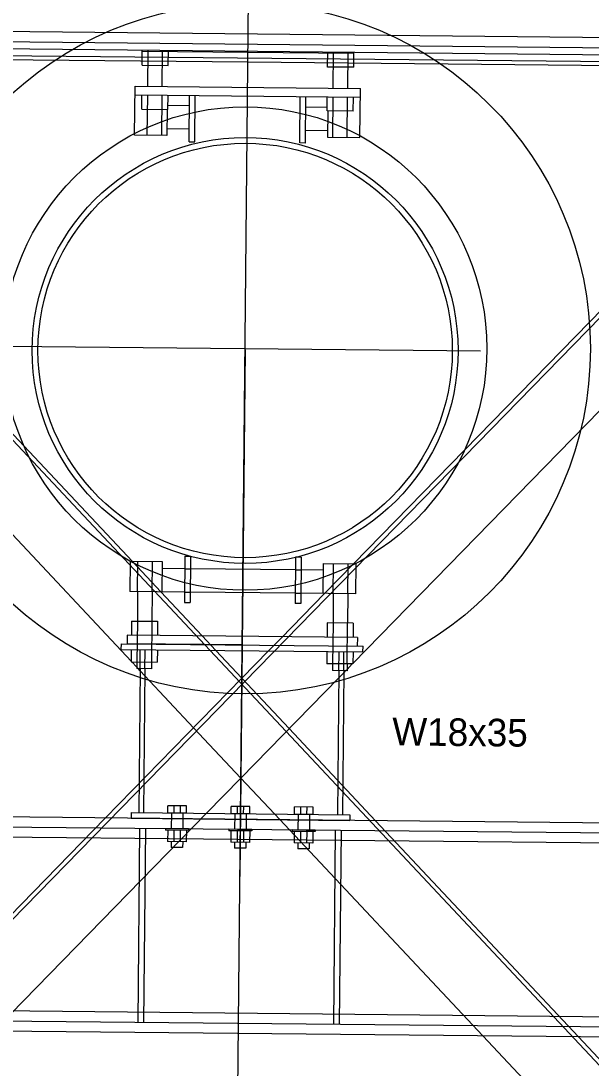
# Model space of a CAD drawing. Extents: x 632312 to 632885, y 378199 to 378534.
# Drawn here: x 632368.08 to 632372.21, y 378385.31 to 378392.89 of the extents above; entities that cross this region are included whole.
import ezdxf

# ---------------------------------------------------------------- set-up
doc = ezdxf.new("R2010")
doc.units = 0
for name, color, linetype in [('B_Boring', 7, 'Continuous'), ('R_Border', 7, 'Continuous'), ('R_Proposed Const Limits Cut', 7, 'Continuous'), ('R_Road Edge of Shoulder', 7, 'Continuous'), ('SHT_Dimensions', 7, 'Continuous')]:
    doc.layers.add(name, color=color, linetype=linetype)

msp = doc.modelspace()

# ---------------------------------------------------------------- linework, layer by layer
at = {"layer": 'B_Boring'}
for p, q in [((632375.2263, 378392.6104), (632364.2269, 378392.7198)), ((632375.2268, 378392.6608), (632364.2274, 378392.7702)), ((632368.9597, 378392.5654), (632368.9607, 378392.6727)), ((632370.4924, 378392.6503), (632368.9607, 378392.6655)), ((632369.0003, 378392.4123), (632369.0029, 378392.6723)), ((632369.1051, 378392.4113), (632369.1077, 378392.6713)), ((632369.1488, 378392.5635), (632369.1499, 378392.6708)), ((632370.3023, 378392.552), (632370.3033, 378392.6594)), ((632370.3429, 378392.399), (632370.3455, 378392.659)), ((632370.4477, 378392.3979), (632370.4503, 378392.6579)), ((632370.4914, 378392.5502), (632370.4925, 378392.6575)), ((632365.1844, 378392.6342), (632369.7259, 378392.5891)), ((632368.9597, 378392.5654), (632369.1488, 378392.5635)), ((632369.7259, 378392.5891), (632374.2673, 378392.5439)), ((632370.4914, 378392.5502), (632370.3023, 378392.552)), ((632368.9043, 378392.0583), (632368.9078, 378392.4132)), ((632368.9078, 378392.4132), (632370.5403, 378392.397)), ((632368.9072, 378392.35), (632370.5396, 378392.3338)), ((632368.9565, 378392.2474), (632368.9575, 378392.3495)), ((632368.9968, 378392.0574), (632368.9997, 378392.3491)), ((632369.1016, 378392.0564), (632369.1045, 378392.3481)), ((632369.1457, 378392.2455), (632369.1467, 378392.3477)), ((632369.2988, 378392.0103), (632369.3021, 378392.3461)), ((632369.3398, 378392.0099), (632369.3432, 378392.3457)), ((632370.1003, 378392.0023), (632370.1036, 378392.3381)), ((632370.1414, 378392.0019), (632370.1447, 378392.3377)), ((632370.2991, 378392.2341), (632370.3001, 378392.3362)), ((632370.3394, 378392.044), (632370.3423, 378392.3358)), ((632370.4442, 378392.043), (632370.4471, 378392.3347)), ((632370.4883, 378392.2322), (632370.4893, 378392.3343)), ((632370.5367, 378392.0421), (632370.5403, 378392.397)), ((632369.3013, 378392.2712), (632369.1459, 378392.2727)), ((632370.144, 378392.2628), (632370.2994, 378392.2613)), ((632368.9565, 378392.2474), (632369.1457, 378392.2455)), ((632369.1403, 378392.2456), (632369.1384, 378392.056)), ((632370.4883, 378392.2322), (632370.2991, 378392.2341)), ((632370.3045, 378392.234), (632370.3026, 378392.0444)), ((632369.1384, 378392.056), (632368.9043, 378392.0583)), ((632369.2997, 378392.1032), (632369.1389, 378392.1048)), ((632370.1423, 378392.0948), (632370.3031, 378392.0932)), ((632370.3026, 378392.0444), (632370.5367, 378392.0421)), ((632369.2988, 378392.0103), (632369.3398, 378392.0099)), ((632370.1414, 378392.0019), (632370.1003, 378392.0023)), ((632369.2689, 378389.0123), (632369.2656, 378388.6765)), ((632369.2689, 378389.0123), (632369.31, 378389.0119)), ((632369.31, 378389.0119), (632369.3067, 378388.6761)), ((632370.0705, 378389.0044), (632370.0672, 378388.6686)), ((632370.1116, 378389.004), (632370.0705, 378389.0044)), ((632370.1116, 378389.004), (632370.1082, 378388.6682)), ((632368.8736, 378388.9722), (632368.8714, 378388.7554)), ((632369.1077, 378388.9698), (632368.8736, 378388.9722)), ((632369.1056, 378388.7531), (632369.1077, 378388.9698)), ((632370.2698, 378388.7415), (632370.2719, 378388.9583)), ((632370.2719, 378388.9583), (632370.506, 378388.9559)), ((632370.506, 378388.9559), (632370.5039, 378388.7392)), ((632369.268, 378388.9195), (632369.1072, 378388.9211)), ((632370.0696, 378388.9115), (632369.3091, 378388.919)), ((632370.2714, 378388.9095), (632370.1106, 378388.9111)), ((632369.2663, 378388.7515), (632368.8714, 378388.7554)), ((632368.927, 378388.7548), (632368.9248, 378388.5413)), ((632369.0318, 378388.7538), (632369.0296, 378388.5403)), ((632370.0679, 378388.7435), (632369.3074, 378388.7511)), ((632370.5039, 378388.7392), (632370.109, 378388.7431)), ((632370.3436, 378388.7408), (632370.3414, 378388.5273)), ((632370.4484, 378388.7397), (632370.4462, 378388.5262)), ((632369.2656, 378388.6765), (632369.3067, 378388.6761)), ((632370.1082, 378388.6682), (632370.0672, 378388.6686)), ((632368.8827, 378388.5418), (632368.8816, 378388.4396)), ((632368.8827, 378388.5418), (632369.0718, 378388.5399)), ((632369.0718, 378388.5399), (632369.0708, 378388.4377)), ((632370.2993, 378388.5277), (632370.2982, 378388.4255)), ((632370.4884, 378388.5258), (632370.2993, 378388.5277)), ((632370.4884, 378388.5258), (632370.4874, 378388.4237)), ((632368.8512, 378388.4399), (632368.8506, 378388.3767)), ((632370.5178, 378388.4234), (632368.8512, 378388.4399)), ((632370.5178, 378388.4234), (632370.5172, 378388.3602)), ((632368.8085, 378388.3355), (632368.8089, 378388.3772)), ((632368.8085, 378388.3355), (632370.5584, 378388.3181)), ((632368.8089, 378388.3772), (632370.5589, 378388.3598)), ((632368.8806, 378388.3348), (632368.8797, 378388.2467)), ((632369.0698, 378388.3329), (632369.0689, 378388.2449)), ((632370.2972, 378388.3207), (632370.2963, 378388.2326)), ((632370.4864, 378388.3188), (632370.4855, 378388.2308)), ((632370.5584, 378388.3181), (632370.5589, 378388.3598)), ((632368.8797, 378388.2467), (632369.0689, 378388.2449)), ((632368.9219, 378388.2463), (632368.9214, 378388.1973)), ((632369.0267, 378388.2453), (632369.0262, 378388.1963)), ((632369.0262, 378388.1963), (632368.9214, 378388.1973)), ((632368.9447, 378388.1971), (632368.9343, 378387.1546)), ((632368.9801, 378388.1967), (632368.9697, 378387.1542)), ((632370.4855, 378388.2308), (632370.2963, 378388.2326)), ((632370.3385, 378388.2322), (632370.338, 378388.1832)), ((632370.4428, 378388.1822), (632370.338, 378388.1832)), ((632370.3842, 378388.1828), (632370.3738, 378387.1402)), ((632370.4196, 378388.1824), (632370.4092, 378387.1399)), ((632370.4433, 378388.2312), (632370.4428, 378388.1822)), ((632369.1457, 378387.1525), (632369.1463, 378387.2045)), ((632369.2817, 378387.2032), (632369.1463, 378387.2045)), ((632369.1909, 378387.152), (632369.1914, 378387.2041)), ((632369.236, 378387.1516), (632369.2365, 378387.2036)), ((632369.2811, 378387.1511), (632369.2817, 378387.2032)), ((632369.6041, 378387.1479), (632369.6046, 378387.2)), ((632369.74, 378387.1986), (632369.6046, 378387.2)), ((632369.6492, 378387.1475), (632369.6497, 378387.1995)), ((632369.6943, 378387.147), (632369.6948, 378387.1991)), ((632369.7395, 378387.1466), (632369.74, 378387.1986)), ((632370.0624, 378387.1433), (632370.0629, 378387.1954)), ((632370.1983, 378387.1941), (632370.0629, 378387.1954)), ((632370.1075, 378387.1429), (632370.108, 378387.195)), ((632370.1526, 378387.1424), (632370.1532, 378387.1945)), ((632370.1978, 378387.142), (632370.1983, 378387.1941)), ((632375.1711, 378387.0509), (632364.1716, 378387.1602)), ((632368.8801, 378387.1551), (632368.8797, 378387.1134)), ((632368.8797, 378387.1134), (632370.463, 378387.0977)), ((632368.8801, 378387.1551), (632370.4634, 378387.1394)), ((632369.2811, 378387.1511), (632369.1457, 378387.1525)), ((632369.1718, 378387.1522), (632369.1706, 378387.038)), ((632369.2551, 378387.1514), (632369.254, 378387.0372)), ((632369.7395, 378387.1466), (632369.6041, 378387.1479)), ((632369.6301, 378387.1476), (632369.629, 378387.0335)), ((632369.7134, 378387.1468), (632369.7123, 378387.0327)), ((632370.1978, 378387.142), (632370.0624, 378387.1433)), ((632370.0884, 378387.1431), (632370.0873, 378387.0289)), ((632370.1717, 378387.1423), (632370.1706, 378387.0281)), ((632370.4634, 378387.1394), (632370.463, 378387.0977)), ((632375.1703, 378386.9784), (632364.1709, 378387.0877)), ((632369.129, 378387.0385), (632369.1289, 378387.028)), ((632369.2955, 378387.0264), (632369.1289, 378387.028)), ((632369.2956, 378387.0368), (632369.129, 378387.0385)), ((632369.1445, 378387.0279), (632369.1437, 378386.9446)), ((632369.1896, 378387.0274), (632369.1888, 378386.9441)), ((632369.2956, 378387.0368), (632369.2955, 378387.0264)), ((632369.5873, 378387.0339), (632369.5872, 378387.0235)), ((632369.7539, 378387.0322), (632369.5873, 378387.0339)), ((632369.7539, 378387.0322), (632369.7538, 378387.0218)), ((632370.0456, 378387.0293), (632370.0455, 378387.0189)), ((632370.2123, 378387.0277), (632370.0456, 378387.0293)), ((632370.2123, 378387.0277), (632370.2122, 378387.0173)), ((632369.2348, 378387.027), (632369.2339, 378386.9437)), ((632369.2799, 378387.0265), (632369.2791, 378386.9432)), ((632369.7538, 378387.0218), (632369.5872, 378387.0235)), ((632369.6028, 378387.0233), (632369.602, 378386.94)), ((632369.6479, 378387.0229), (632369.6471, 378386.9395)), ((632369.6931, 378387.0224), (632369.6923, 378386.9391)), ((632369.7382, 378387.022), (632369.7374, 378386.9386)), ((632370.2122, 378387.0173), (632370.0455, 378387.0189)), ((632370.0611, 378387.0188), (632370.0603, 378386.9354)), ((632370.1063, 378387.0183), (632370.1054, 378386.935)), ((632370.1514, 378387.0179), (632370.1506, 378386.9345)), ((632370.1965, 378387.0174), (632370.1957, 378386.9341)), ((632369.2791, 378386.9432), (632369.1437, 378386.9446)), ((632369.1697, 378386.9443), (632369.1693, 378386.9026)), ((632369.2526, 378386.9018), (632369.1693, 378386.9026)), ((632369.253, 378386.9435), (632369.2526, 378386.9018)), ((632369.7374, 378386.9386), (632369.602, 378386.94)), ((632369.628, 378386.9397), (632369.6276, 378386.8981)), ((632369.7109, 378386.8972), (632369.6276, 378386.8981)), ((632369.7114, 378386.9389), (632369.7109, 378386.8972)), ((632370.1957, 378386.9341), (632370.0603, 378386.9354)), ((632370.0863, 378386.9352), (632370.0859, 378386.8935)), ((632370.1692, 378386.8927), (632370.0859, 378386.8935)), ((632370.1697, 378386.9344), (632370.1692, 378386.8927)), ((632375.1564, 378385.5735), (632364.1569, 378385.6828)), ((632375.1557, 378385.501), (632364.1562, 378385.6103))]:
    msp.add_line(p, q, dxfattribs=at)
for points in [[(632370.4855, 378388.2352), (632374.2629, 378392.1028), (632373.9052, 378392.4521), (632370.4907, 378388.9561)], [(632367.991, 378389.9288), (632368.8889, 378388.972)], [(632368.8798, 378388.2512), (632367.9838, 378389.2058)], [(632369.0944, 378388.7532), (632369.3934, 378388.4345)], [(632370.281, 378388.7414), (632369.9656, 378388.4184)], [(632369.8742, 378388.3249), (632369.6815, 378388.1276), (632368.6928, 378387.1153)], [(632369.4928, 378388.3287), (632369.6815, 378388.1276)], [(632368.9215, 378388.2067), (632368.884, 378388.2467)], [(632368.9445, 378388.1822), (632368.9304, 378388.1972)], [(632370.4194, 378388.1676), (632370.4338, 378388.1823)], [(632370.4429, 378388.1916), (632370.4812, 378388.2308)], [(632369.3318, 378387.7696), (632368.9796, 378388.1449)], [(632369.4253, 378387.1497), (632369.6743, 378387.4046), (632370.3837, 378388.1309)], [(632370.024, 378387.7627), (632370.6499, 378387.0958)], [(632369.9182, 378387.1448), (632369.6743, 378387.4046)], [(632373.8112, 378382.997), (632371.4263, 378385.538)], [(632372.1184, 378385.5312), (632374.1758, 378383.3392)]]:
    msp.add_lwpolyline(points, dxfattribs=at)
for radius in [1.5417, 1.5]:
    msp.add_circle((632369.7051, 378390.5001), radius, dxfattribs=at)
at = {"layer": 'R_Border'}
for radius in [2.5, 1.75]:
    msp.add_circle((632369.7052, 378390.5142), radius, dxfattribs=at)
at = {"layer": 'R_Proposed Const Limits Cut'}
for p, q in [((632375.2276, 378392.7354), (632364.2281, 378392.8448)), ((632374.2676, 378392.57), (632365.1847, 378392.6603)), ((632365.5218, 378392.5139), (632374.153, 378383.3178)), ((632373.9276, 378392.4303), (632365.1153, 378383.4076)), ((632369.0955, 378388.7532), (632368.8889, 378388.972)), ((632368.927, 378388.7548), (632368.9291, 378388.9716)), ((632369.0318, 378388.7538), (632369.0339, 378388.9706)), ((632370.281, 378388.7414), (632370.4907, 378388.9561)), ((632370.3436, 378388.7408), (632370.3457, 378388.9575)), ((632370.4484, 378388.7397), (632370.4505, 378388.9565)), ((632369.268, 378388.9195), (632369.3091, 378388.919)), ((632370.0696, 378388.9115), (632370.1106, 378388.9111)), ((632369.2663, 378388.7515), (632369.3074, 378388.7511)), ((632370.0679, 378388.7435), (632370.109, 378388.7431)), ((632368.9248, 378388.5413), (632368.9219, 378388.2463)), ((632369.0296, 378388.5403), (632369.0267, 378388.2453)), ((632370.3414, 378388.5273), (632370.3385, 378388.2322)), ((632370.4433, 378388.2312), (632370.4462, 378388.5262)), ((632369.4928, 378388.3287), (632369.3934, 378388.4345)), ((632369.8742, 378388.3249), (632369.9656, 378388.4184)), ((632368.9447, 378388.1971), (632368.946, 378388.3341)), ((632368.9801, 378388.1967), (632368.9814, 378388.3338)), ((632370.3842, 378388.1828), (632370.3855, 378388.3198)), ((632370.4196, 378388.1824), (632370.4209, 378388.3195)), ((632368.8798, 378388.2512), (632368.884, 378388.2467)), ((632368.9215, 378388.2067), (632368.9304, 378388.1972)), ((632368.9445, 378388.1822), (632368.9796, 378388.1449)), ((632370.3837, 378388.1309), (632370.4194, 378388.1676)), ((632370.4338, 378388.1823), (632370.4429, 378388.1916)), ((632370.4812, 378388.2308), (632370.4855, 378388.2352)), ((632370.024, 378387.7627), (632369.6815, 378388.1276)), ((632369.3318, 378387.7696), (632369.6743, 378387.4046)), ((632368.6928, 378387.1153), (632367.1934, 378385.5801)), ((632367.8856, 378385.5732), (632369.4253, 378387.1497)), ((632369.9182, 378387.1448), (632371.4263, 378385.538)), ((632370.6499, 378387.0958), (632372.1184, 378385.5312)), ((632375.1696, 378386.9051), (632364.1702, 378387.0144)), ((632375.1571, 378385.6468), (632364.1577, 378385.7561))]:
    msp.add_line(p, q, dxfattribs=at)
at = {"layer": 'R_Road Edge of Shoulder'}
msp.add_line((632369.5749, 378377.4056), (632369.9054, 378410.6473), dxfattribs=at)
at = {"layer": 'SHT_Dimensions'}
for p, q in [((632367.9895, 378390.5312), (632371.41, 378390.4972)), ((632369.7051, 378390.5038), (632369.6672, 378386.6922)), ((632369.6839, 378388.3685), (632368.8506, 378388.3767)), ((632368.9415, 378387.0403), (632368.9275, 378385.6354)), ((632368.9832, 378387.0399), (632368.9692, 378385.635)), ((632370.3581, 378387.0262), (632370.3441, 378385.6213)), ((632370.3997, 378387.0258), (632370.3858, 378385.6209))]:
    msp.add_line(p, q, dxfattribs=at)

# ---------------------------------------------------------------- texts
msp.add_text('W18x35', height=0.2, rotation=359.43036, dxfattribs=at).set_placement((632370.7698, 378387.6415))

doc.saveas('drawing.dxf')
